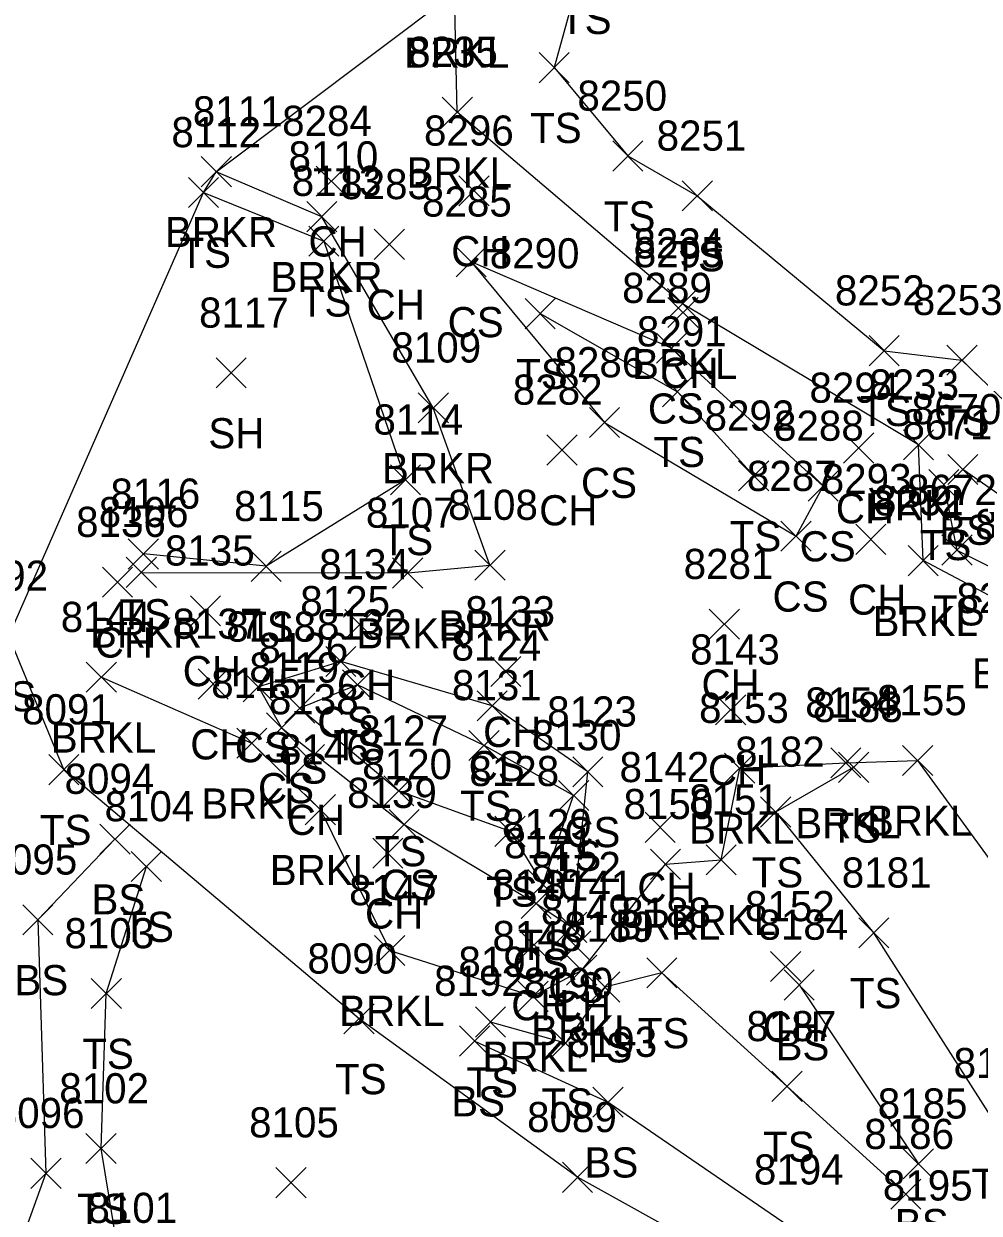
# Model space of a CAD drawing. Extents: x 1482574 to 1485769, y 580696 to 595649.
# Drawn here: x 1484969 to 1485032.3, y 581565.4 to 581644.3 of the extents above; entities that cross this region are included whole.
import ezdxf

# ---------------------------------------------------------------- set-up
doc = ezdxf.new("R2010")
doc.units = 0
for name, color, linetype in [('L_A', 7, 'Continuous'), ('L_I', 7, 'Continuous'), ('L_TIC', 7, 'Continuous'), ('LAWE', 7, 'Continuous'), ('LELB', 7, 'Continuous'), ('LSOGP', 7, 'Continuous')]:
    doc.layers.add(name, color=color, linetype=linetype)

msp = doc.modelspace()

# ---------------------------------------------------------------- linework, layer by layer
at = {"layer": 'L_TIC'}
for points in [[(1485003.126, 581640.419), (1485005.126, 581642.419)], [(1485005.126, 581640.419), (1485003.126, 581642.419)], [(1484996.706, 581637.469), (1484998.706, 581639.469)], [(1484998.706, 581637.469), (1484996.706, 581639.469)], [(1485008.012, 581634.559), (1485010.012, 581636.559)], [(1485010.012, 581634.559), (1485008.012, 581636.559)], [(1484980.735, 581633.519), (1484982.735, 581635.519)], [(1484982.735, 581633.519), (1484980.735, 581635.519)], [(1484988.356, 581632.893), (1484990.356, 581634.893)], [(1484990.356, 581632.893), (1484988.356, 581634.893)], [(1484997.815, 581632.246), (1484999.815, 581634.246)], [(1484999.815, 581632.246), (1484997.815, 581634.246)], [(1484979.882, 581632.141), (1484981.882, 581634.141)], [(1484981.882, 581632.141), (1484979.882, 581634.141)], [(1485012.611, 581631.912), (1485014.611, 581633.912)], [(1485014.611, 581631.912), (1485012.611, 581633.912)], [(1484987.733, 581630.534), (1484989.733, 581632.534)], [(1484989.733, 581630.534), (1484987.733, 581632.534)], [(1484987.857, 581628.91), (1484989.857, 581630.91)], [(1484989.857, 581628.91), (1484987.857, 581630.91)], [(1484992.205, 581628.696), (1484994.205, 581630.696)], [(1484994.205, 581628.696), (1484992.205, 581630.696)], [(1484997.628, 581627.541), (1484999.628, 581629.541)], [(1484999.628, 581627.541), (1484997.628, 581629.541)], [(1485011.643, 581624.763), (1485013.643, 581626.763)], [(1485013.643, 581624.763), (1485011.643, 581626.763)], [(1485002.201, 581624.103), (1485004.201, 581626.103)], [(1485004.201, 581624.103), (1485002.201, 581626.103)], [(1485011.666, 581624.179), (1485013.666, 581626.179)], [(1485013.666, 581624.179), (1485011.666, 581626.179)], [(1485010.899, 581621.813), (1485012.899, 581623.813)], [(1485012.899, 581621.813), (1485010.899, 581623.813)], [(1485024.996, 581621.646), (1485026.996, 581623.646)], [(1485026.996, 581621.646), (1485024.996, 581623.646)], [(1485030.157, 581621.013), (1485032.157, 581623.013)], [(1485032.157, 581621.013), (1485030.157, 581623.013)], [(1484981.716, 581620.173), (1484983.716, 581622.173)], [(1484983.716, 581620.173), (1484981.716, 581622.173)], [(1485011.302, 581618.929), (1485013.302, 581620.929)], [(1485013.302, 581618.929), (1485011.302, 581620.929)], [(1484995.118, 581617.86), (1484997.118, 581619.86)], [(1484997.118, 581617.86), (1484995.118, 581619.86)], [(1485006.463, 581616.882), (1485008.463, 581618.882)], [(1485008.463, 581616.882), (1485006.463, 581618.882)], [(1485003.645, 581615.064), (1485005.645, 581617.064)], [(1485005.645, 581615.064), (1485003.645, 581617.064)], [(1485023.307, 581615.196), (1485025.307, 581617.196)], [(1485025.307, 581615.196), (1485023.307, 581617.196)], [(1485027.273, 581615.406), (1485029.273, 581617.406)], [(1485029.273, 581615.406), (1485027.273, 581617.406)], [(1485016.355, 581613.345), (1485018.355, 581615.345)], [(1485018.355, 581613.345), (1485016.355, 581615.345)], [(1485030.213, 581613.772), (1485032.213, 581615.772)], [(1485032.213, 581613.772), (1485030.213, 581615.772)], [(1484993.277, 581613.086), (1484995.277, 581615.086)], [(1484995.277, 581613.086), (1484993.277, 581615.086)], [(1485020.958, 581612.673), (1485022.958, 581614.673)], [(1485022.958, 581612.673), (1485020.958, 581614.673)], [(1485028.953, 581612.758), (1485030.953, 581614.758)], [(1485030.953, 581612.758), (1485028.953, 581614.758)], [(1485019.16, 581609.343), (1485021.16, 581611.343)], [(1485021.16, 581609.343), (1485019.16, 581611.343)], [(1485024.12, 581609.139), (1485026.12, 581611.139)], [(1485026.12, 581609.139), (1485024.12, 581611.139)], [(1484975.899, 581608.168), (1484977.899, 581610.168)], [(1484977.899, 581608.168), (1484975.899, 581610.168)], [(1485029.823, 581608.424), (1485031.823, 581610.424)], [(1485031.823, 581608.424), (1485029.823, 581610.424)], [(1484984.039, 581607.348), (1484986.039, 581609.348)], [(1484986.039, 581607.348), (1484984.039, 581609.348)], [(1484998.871, 581607.427), (1485000.871, 581609.427)], [(1485000.871, 581607.427), (1484998.871, 581609.427)], [(1485027.582, 581607.722), (1485029.582, 581609.722)], [(1485029.582, 581607.722), (1485027.582, 581609.722)], [(1484974.189, 581606.295), (1484976.189, 581608.295)], [(1484976.189, 581606.295), (1484974.189, 581608.295)], [(1484975.768, 581606.944), (1484977.768, 581608.944)], [(1484977.768, 581606.944), (1484975.768, 581608.944)], [(1484993.422, 581606.908), (1484995.422, 581608.908)], [(1484995.422, 581606.908), (1484993.422, 581608.908)], [(1484980.02, 581604.398), (1484982.02, 581606.398)], [(1484982.02, 581604.398), (1484980.02, 581606.398)], [(1484990.246, 581603.486), (1484992.246, 581605.486)], [(1484992.246, 581603.486), (1484990.246, 581605.486)], [(1485014.403, 581603.506), (1485016.403, 581605.506)], [(1485016.403, 581603.506), (1485014.403, 581605.506)], [(1484988.989, 581601.039), (1484990.989, 581603.039)], [(1484990.989, 581601.039), (1484988.989, 581603.039)], [(1484973.117, 581599.992), (1484975.117, 581601.992)], [(1484975.117, 581599.992), (1484973.117, 581601.992)], [(1484999.928, 581600.366), (1485001.928, 581602.366)], [(1485001.928, 581600.366), (1484999.928, 581602.366)], [(1484980.522, 581599.54), (1484982.522, 581601.54)], [(1484982.522, 581599.54), (1484980.522, 581601.54)], [(1484983.52, 581599.353), (1484985.52, 581601.353)], [(1484985.52, 581599.353), (1484983.52, 581601.353)], [(1484990.095, 581599.487), (1484992.095, 581601.487)], [(1484992.095, 581599.487), (1484990.095, 581601.487)], [(1484986.27, 581597.935), (1484988.27, 581599.935)], [(1484988.27, 581597.935), (1484986.27, 581599.935)], [(1484999.019, 581598.096), (1485001.019, 581600.096)], [(1485001.019, 581598.096), (1484999.019, 581600.096)], [(1485014.829, 581597.834), (1485016.829, 581599.834)], [(1485016.829, 581597.834), (1485014.829, 581599.834)], [(1484985.056, 581596.636), (1484987.056, 581598.636)], [(1484987.056, 581596.636), (1484985.056, 581598.636)], [(1484983.09, 581595.616), (1484985.09, 581597.616)], [(1484985.09, 581595.616), (1484983.09, 581597.616)], [(1484998.481, 581595.468), (1485000.481, 581597.468)], [(1485000.481, 581595.468), (1484998.481, 581597.468)], [(1484986.913, 581594.533), (1484988.913, 581596.533)], [(1484988.913, 581594.533), (1484986.913, 581596.533)], [(1485027.214, 581594.474), (1485029.214, 581596.474)], [(1485029.214, 581594.474), (1485027.214, 581596.474)], [(1484970.633, 581593.864), (1484972.633, 581595.864)], [(1484972.633, 581593.864), (1484970.633, 581595.864)], [(1485005.357, 581593.719), (1485007.357, 581595.719)], [(1485007.357, 581593.719), (1485005.357, 581595.719)], [(1485015.423, 581593.962), (1485017.423, 581595.962)], [(1485017.423, 581593.962), (1485015.423, 581595.962)], [(1485022.46, 581594.316), (1485024.46, 581596.316)], [(1485024.46, 581594.316), (1485022.46, 581596.316)], [(1485022.972, 581594.018), (1485024.972, 581596.018)], [(1485024.972, 581594.018), (1485022.972, 581596.018)], [(1484992.831, 581592.456), (1484994.831, 581594.456)], [(1484994.831, 581592.456), (1484992.831, 581594.456)], [(1485004.419, 581592.148), (1485006.419, 581594.148)], [(1485006.419, 581592.148), (1485004.419, 581594.148)], [(1484987.631, 581591.206), (1484989.631, 581593.206)], [(1484989.631, 581591.206), (1484987.631, 581593.206)], [(1485017.808, 581591.055), (1485019.808, 581593.055)], [(1485019.808, 581591.055), (1485017.808, 581593.055)], [(1484993.186, 581590.229), (1484995.186, 581592.229)], [(1484995.186, 581590.229), (1484993.186, 581592.229)], [(1485000.2, 581589.773), (1485002.2, 581591.773)], [(1485002.2, 581589.773), (1485000.2, 581591.773)], [(1485010.151, 581590.035), (1485012.151, 581592.035)], [(1485012.151, 581590.035), (1485010.151, 581592.035)], [(1484974.016, 581589.257), (1484976.016, 581591.257)], [(1484976.016, 581589.257), (1484974.016, 581591.257)], [(1484992.103, 581588.322), (1484994.103, 581590.322)], [(1484994.103, 581588.322), (1484992.103, 581590.322)], [(1484976.099, 581587.437), (1484978.099, 581589.437)], [(1484978.099, 581587.437), (1484976.099, 581589.437)], [(1485010.505, 581587.584), (1485012.505, 581589.584)], [(1485012.505, 581587.584), (1485010.505, 581589.584)], [(1485014.199, 581587.886), (1485016.199, 581589.886)], [(1485016.199, 581587.886), (1485014.199, 581589.886)], [(1485002.372, 581586.246), (1485004.372, 581588.246)], [(1485004.372, 581586.246), (1485002.372, 581588.246)], [(1485001.936, 581584.986), (1485003.936, 581586.986)], [(1485003.936, 581584.986), (1485001.936, 581586.986)], [(1484968.907, 581583.903), (1484970.907, 581585.903)], [(1484970.907, 581583.903), (1484968.907, 581585.903)], [(1485004.291, 581583.408), (1485006.291, 581585.408)], [(1485006.291, 581583.408), (1485004.291, 581585.408)], [(1485024.314, 581583.04), (1485026.314, 581585.04)], [(1485026.314, 581583.04), (1485024.314, 581585.04)], [(1484992.228, 581581.872), (1484994.228, 581583.872)], [(1484994.228, 581581.872), (1484992.228, 581583.872)], [(1485001.794, 581582.24), (1485003.794, 581584.24)], [(1485003.794, 581582.24), (1485001.794, 581584.24)], [(1485004.55, 581582.171), (1485006.55, 581584.171)], [(1485006.55, 581582.171), (1485004.55, 581584.171)], [(1485004.954, 581580.57), (1485006.954, 581582.57)], [(1485006.954, 581580.57), (1485004.954, 581582.57)], [(1485010.262, 581580.383), (1485012.262, 581582.383)], [(1485012.262, 581580.383), (1485010.262, 581582.383)], [(1485018.468, 581580.813), (1485020.468, 581582.813)], [(1485020.468, 581580.813), (1485018.468, 581582.813)], [(1485006.486, 581579.444), (1485008.486, 581581.444)], [(1485008.486, 581579.444), (1485006.486, 581581.444)], [(1485019.36, 581579.582), (1485021.36, 581581.582)], [(1485021.36, 581579.582), (1485019.36, 581581.582)], [(1484973.441, 581579.018), (1484975.441, 581581.018)], [(1484975.441, 581579.018), (1484973.441, 581581.018)], [(1485001.732, 581578.831), (1485003.732, 581580.831)], [(1485003.732, 581578.831), (1485001.732, 581580.831)], [(1484990.197, 581577.338), (1484992.197, 581579.338)], [(1484992.197, 581577.338), (1484990.197, 581579.338)], [(1484998.907, 581577.125), (1485000.907, 581579.125)], [(1485000.907, 581577.125), (1484998.907, 581579.125)], [(1484997.861, 581575.862), (1484999.861, 581577.862)], [(1484999.861, 581575.862), (1484997.861, 581577.862)], [(1485003.874, 581575.721), (1485005.874, 581577.721)], [(1485005.874, 581575.721), (1485003.874, 581577.721)], [(1485018.563, 581572.857), (1485020.563, 581574.857)], [(1485020.563, 581572.857), (1485018.563, 581574.857)], [(1485006.696, 581571.813), (1485008.696, 581573.813)], [(1485008.696, 581571.813), (1485006.696, 581573.813)], [(1484973.097, 581568.733), (1484975.097, 581570.733)], [(1484975.097, 581568.733), (1484973.097, 581570.733)], [(1485027.264, 581567.725), (1485029.264, 581569.725)], [(1485029.264, 581567.725), (1485027.264, 581569.725)], [(1484969.442, 581567.095), (1484971.442, 581569.095)], [(1484971.442, 581567.095), (1484969.442, 581569.095)], [(1485004.678, 581566.826), (1485006.678, 581568.826)], [(1485006.678, 581566.826), (1485004.678, 581568.826)], [(1484985.679, 581566.472), (1484987.679, 581568.472)], [(1484987.679, 581566.472), (1484985.679, 581568.472)], [(1485026.43, 581565.704), (1485028.43, 581567.704)], [(1485028.43, 581565.704), (1485026.43, 581567.704)]]:
    msp.add_lwpolyline(points, dxfattribs=at)
at = {"layer": 'LAWE'}
for points in [[(1485099.1, 581556.13), (1485088.398, 581562), (1485080.442, 581567.692), (1485075.58, 581577.374), (1485071.961, 581583.594), (1485063.273, 581587.249), (1485048.48, 581598.528), (1485035.166, 581605.248), (1485028.582, 581608.722), (1485028.273, 581616.406), (1485012.643, 581625.763), (1484997.706, 581638.469), (1484997.519, 581646.409), (1484999.248, 581659.608), (1485005.947, 581671.579), (1485014.32, 581682.767), (1485017.407, 581703.738), (1485017.263, 581721.947)], [(1484976.768, 581607.944), (1484994.422, 581607.908), (1484999.871, 581608.427), (1484996.118, 581618.86), (1484988.733, 581631.534), (1484981.735, 581634.519)], [(1484974.117, 581600.992), (1484984.09, 581596.616), (1484988.631, 581592.206), (1484993.228, 581582.872), (1485002.732, 581579.831), (1485005.954, 581581.57), (1485011.505, 581588.584), (1485015.199, 581588.886), (1485016.423, 581594.962), (1485023.46, 581595.316), (1485028.214, 581595.474), (1485036.863, 581583.581), (1485036.065, 581574.657), (1485046.886, 581565.989), (1485054.684, 581560.34), (1485062.22, 581551.186)]]:
    msp.add_lwpolyline(points, dxfattribs=at)
at = {"layer": 'LELB'}
for points in [[(1485021.203, 581722.829), (1485019.576, 581708.682), (1485018.923, 581696.31), (1485015.291, 581681.681), (1485009.596, 581676.337), (1485004.149, 581657.718), (1485006.105, 581648.646), (1485004.126, 581641.419), (1485009.012, 581635.559), (1485013.611, 581632.912), (1485025.996, 581622.646), (1485031.157, 581622.013), (1485040.905, 581612.626), (1485044.792, 581604.06), (1485054.025, 581597.429), (1485058.231, 581593.289), (1485067.079, 581592.183), (1485075.865, 581590.559), (1485078.352, 581585.917), (1485082.988, 581583.45), (1485084.989, 581579.68), (1485093.818, 581577.557), (1485099.497, 581571.757), (1485106.862, 581568.984)], [(1484980.882, 581633.141), (1484988.857, 581629.91), (1484994.277, 581614.086), (1484985.039, 581608.348), (1484976.899, 581609.168)], [(1484998.628, 581628.541), (1485007.463, 581617.882), (1485020.16, 581610.343), (1485021.958, 581613.673), (1485011.899, 581622.813)], [(1485011.899, 581622.813), (1484998.628, 581628.541)], [(1485003.201, 581625.103), (1485012.302, 581619.929), (1485017.355, 581614.345)], [(1485037.519, 581606.543), (1485037.45, 581610.435), (1485031.213, 581614.772)], [(1485029.953, 581613.758), (1485030.823, 581609.424), (1485035.337, 581607.137)], [(1485097.076, 581506.941), (1485080.77, 581517.807), (1485078.027, 581523.771), (1485062.01, 581528.804), (1485049.09, 581536.209), (1485040.813, 581538.65), (1485032.027, 581549.267), (1485022.483, 581558.483), (1485005.678, 581567.826), (1484991.197, 581578.338), (1484971.633, 581594.864), (1484967.972, 581603.725)], [(1484984.52, 581600.353), (1484986.056, 581597.636), (1484994.186, 581591.229), (1485002.936, 581585.986), (1485005.291, 581584.408), (1485006.357, 581594.719), (1485000.019, 581599.096), (1484989.989, 581602.039)], [(1484989.989, 581602.039), (1484984.52, 581600.353)], [(1484987.27, 581598.935), (1484993.831, 581593.456), (1485001.2, 581590.773), (1485003.372, 581587.246), (1485005.419, 581593.148), (1484999.481, 581596.468), (1484991.095, 581600.487)], [(1484991.095, 581600.487), (1484987.27, 581598.935)], [(1485044.901, 581562.551), (1485033.382, 581571.406), (1485025.314, 581584.04), (1485018.808, 581592.055), (1485023.972, 581595.018)], [(1484975.016, 581590.257), (1484969.907, 581584.903), (1484970.442, 581568.095), (1484966.049, 581555.943), (1484956.4, 581551.842)], [(1484955.856, 581543.834), (1484964.14, 581549.172), (1484975.396, 581561.803), (1484974.097, 581569.733), (1484974.441, 581580.018), (1484977.099, 581588.437)], [(1485027.43, 581566.704), (1485019.563, 581573.857), (1485011.262, 581581.383), (1485007.486, 581580.444), (1485004.874, 581576.721), (1484999.907, 581578.125)], [(1485020.36, 581580.582), (1485028.264, 581568.725)], [(1484998.861, 581576.862), (1485007.696, 581572.813), (1485020.058, 581564.349), (1485028.605, 581563.289), (1485031.813, 581560.09)]]:
    msp.add_lwpolyline(points, dxfattribs=at)
at = {"layer": 'LSOGP'}
msp.add_lwpolyline([(1484923.771, 581416.282), (1484922.142, 581457.704), (1484921.818, 581525.617), (1484923.517, 581536.406), (1484956.4, 581551.842), (1484958.467, 581576.934), (1484967.972, 581603.725), (1484980.882, 581633.141), (1484981.735, 581634.519), (1484997.519, 581646.409), (1484999.248, 581659.608), (1485005.947, 581671.579), (1485014.32, 581682.767), (1485017.407, 581703.738), (1485017.263, 581721.947), (1485021.203, 581722.829), (1485060.77, 581735.5), (1485092.404, 581773.469)], dxfattribs=at)

# ---------------------------------------------------------------- texts
at = {"layer": 'L_A'}
for s, p in [('TS', (1485004.514, 581643.646)), ('BRKL', (1484994.165, 581641.409)), ('TS', (1485002.535, 581636.419)), ('BRKL', (1484994.352, 581633.469)), ('TS', (1485007.421, 581630.559)), ('BRKR', (1484978.326, 581629.519)), ('CH', (1484987.844, 581628.893)), ('CH', (1484997.303, 581628.246)), ('TS', (1484979.291, 581628.141)), ('TS', (1485012.02, 581627.912)), ('BRKR', (1484985.324, 581626.534)), ('TS', (1484987.266, 581624.91)), ('CH', (1484991.693, 581624.696)), ('CS', (1484997.069, 581623.541)), ('BRKL', (1485009.289, 581620.763)), ('TS', (1485001.61, 581620.103)), ('CH', (1485011.154, 581620.179)), ('CS', (1485010.34, 581617.813)), ('TS', (1485024.405, 581617.646)), ('TS', (1485029.566, 581617.013)), ('SH', (1484981.204, 581616.173)), ('TS', (1485010.711, 581614.929)), ('BRKR', (1484992.709, 581613.86)), ('CS', (1485005.904, 581612.882)), ('CH', (1485003.133, 581611.064)), ('CH', (1485022.795, 581611.196)), ('BRKL', (1485024.919, 581611.406)), ('TS', (1485015.764, 581609.345)), ('BS', (1485029.654, 581609.772)), ('TS', (1484992.686, 581609.086)), ('CS', (1485020.399, 581608.673)), ('TS', (1485028.362, 581608.758)), ('CS', (1485018.601, 581605.343)), ('CH', (1485023.608, 581605.139)), ('TS', (1484975.308, 581604.168)), ('TS', (1485029.232, 581604.424)), ('TS', (1484983.448, 581603.348)), ('BRKR', (1484996.462, 581603.427)), ('BRKL', (1485025.228, 581603.722)), ('BRKR', (1484973.359, 581602.944)), ('CH', (1484973.677, 581602.295)), ('BRKR', (1484991.013, 581602.908)), ('CH', (1484979.508, 581600.398)), ('BRKL', (1485031.812, 581600.248)), ('CH', (1484989.734, 581599.486)), ('CH', (1485013.891, 581599.506)), ('TS', (1484966.381, 581598.725)), ('CS', (1484988.43, 581597.039)), ('BRKL', (1484970.763, 581595.992)), ('CH', (1484999.416, 581596.366)), ('CH', (1484980.01, 581595.54)), ('CS', (1484982.961, 581595.353)), ('TS', (1484989.504, 581595.487)), ('TS', (1484985.679, 581593.935)), ('CS', (1484998.46, 581594.096)), ('CH', (1485014.317, 581593.834)), ('CS', (1484984.497, 581592.636)), ('BRKL', (1484980.736, 581591.616)), ('TS', (1484997.89, 581591.468)), ('CH', (1484986.401, 581590.533)), ('BRKL', (1485024.86, 581590.474)), ('TS', (1484970.042, 581589.864)), ('CS', (1485004.798, 581589.719)), ('BRKL', (1485013.069, 581589.962)), ('BRKL', (1485020.106, 581590.316)), ('TS', (1485022.381, 581590.018)), ('TS', (1484992.24, 581588.456)), ('TS', (1485003.828, 581588.148)), ('BRKL', (1484985.277, 581587.206)), ('TS', (1485017.217, 581587.055)), ('CS', (1484992.627, 581586.229)), ('TS', (1484999.609, 581585.773)), ('CH', (1485009.639, 581586.035)), ('BS', (1484973.457, 581585.257)), ('CH', (1484991.591, 581584.322)), ('TS', (1484975.508, 581583.437)), ('BRKL', (1485008.151, 581583.584)), ('BRKL', (1485011.845, 581583.886)), ('TS', (1485001.781, 581582.246)), ('CS', (1485001.377, 581580.986)), ('BS', (1484968.348, 581579.903)), ('CS', (1485003.732, 581579.408)), ('TS', (1485023.723, 581579.04)), ('BRKL', (1484989.874, 581577.872)), ('CH', (1485001.282, 581578.24)), ('CH', (1485004.038, 581578.171)), ('BRKL', (1485002.6, 581576.57)), ('TS', (1485009.671, 581576.383)), ('CH', (1485017.956, 581576.813)), ('TS', (1485005.895, 581575.444)), ('BS', (1485018.801, 581575.582)), ('TS', (1484972.85, 581575.018)), ('BRKL', (1484999.378, 581574.831)), ('TS', (1484989.606, 581573.338)), ('TS', (1484998.316, 581573.125)), ('BS', (1484997.302, 581571.862)), ('TS', (1485003.283, 581571.721)), ('TS', (1485017.972, 581568.857)), ('BS', (1485006.137, 581567.813)), ('TS', (1485031.791, 581566.406)), ('TS', (1484972.506, 581564.733)), ('BS', (1485026.705, 581563.725))]:
    msp.add_text(s, height=2, dxfattribs=at).set_placement(p)
at = {"layer": 'L_I'}
for s, p in [('8235', (1484994.446, 581641.469)), ('8250', (1485005.666, 581638.559)), ('8111', (1484980.176, 581637.519)), ('8112', (1484978.756, 581636.141)), ('8284', (1484986.096, 581636.893)), ('8296', (1484995.5, 581636.246)), ('8251', (1485010.918, 581635.912)), ('8110', (1484986.52, 581634.534)), ('8113', (1484986.731, 581632.91)), ('8283', (1484989.945, 581632.696)), ('8285', (1484995.368, 581631.541)), ('8234', (1485009.383, 581628.763)), ('8290', (1484999.855, 581628.103)), ('8295', (1485009.406, 581628.179)), ('8289', (1485008.631, 581625.813)), ('8252', (1485022.736, 581625.646)), ('8253', (1485027.897, 581625.013)), ('8117', (1484980.59, 581624.173)), ('8291', (1485009.609, 581622.929)), ('8109', (1484993.338, 581621.86)), ('8286', (1485004.148, 581620.882)), ('8282', (1485001.385, 581619.064)), ('8294', (1485021.047, 581619.196)), ('8233', (1485025.013, 581619.406)), ('8292', (1485014.095, 581617.345)), ('8670', (1485027.819, 581617.772)), ('8114', (1484992.151, 581617.086)), ('8288', (1485018.698, 581616.673)), ('8671', (1485027.213, 581616.758)), ('8287', (1485016.9, 581613.343)), ('8293', (1485021.86, 581613.139)), ('8116', (1484974.718, 581612.168)), ('8232', (1485025.322, 581611.722)), ('8672', (1485027.516, 581612.424)), ('8106', (1484973.941, 581610.944)), ('8115', (1484982.913, 581611.348)), ('8107', (1484991.65, 581610.908)), ('8108', (1484997.099, 581611.427)), ('8136', (1484972.441, 581610.295)), ('8673', (1485032.03, 581610.137)), ('8135', (1484978.327, 581608.398)), ('8134', (1484988.553, 581607.486)), ('8281', (1485012.71, 581607.506)), ('8092', (1484964.633, 581606.725)), ('8125', (1484987.296, 581605.039)), ('8280', (1485030.79, 581605.242)), ('8144', (1484971.424, 581603.992)), ('8133', (1484998.235, 581604.366)), ('8137', (1484978.829, 581603.54)), ('8118', (1484982.394, 581603.353)), ('8132', (1484988.402, 581603.487)), ('8126', (1484984.522, 581601.935)), ('8124', (1484997.326, 581602.096)), ('8143', (1485013.136, 581601.834)), ('8119', (1484983.922, 581600.636)), ('8145', (1484981.397, 581599.616)), ('8131', (1484997.355, 581599.468)), ('8138', (1484985.22, 581598.533)), ('8154', (1485020.767, 581598.316)), ('8155', (1485025.521, 581598.474)), ('8091', (1484968.861, 581597.864)), ('8123', (1485003.664, 581597.719)), ('8153', (1485013.73, 581597.962)), ('8183', (1485021.279, 581598.018)), ('8127', (1484991.138, 581596.456)), ('8130', (1485002.639, 581596.148)), ('8146', (1484985.883, 581595.206)), ('8182', (1485016.115, 581595.055)), ('8120', (1484991.406, 581594.229)), ('8128', (1484998.507, 581593.773)), ('8142', (1485008.458, 581594.035)), ('8094', (1484971.677, 581593.257)), ('8139', (1484990.402, 581592.322)), ('8104', (1484974.327, 581591.437)), ('8150', (1485008.725, 581591.584)), ('8151', (1485013.073, 581591.886)), ('8129', (1485000.671, 581590.246)), ('8121', (1485000.81, 581588.986)), ('8095', (1484966.568, 581587.903)), ('8122', (1485002.598, 581587.408)), ('8181', (1485023.188, 581587.04)), ('8147', (1484990.535, 581585.872)), ('8140', (1485000.014, 581586.24)), ('8141', (1485003.424, 581586.171)), ('8149', (1485003.253, 581584.57)), ('8188', (1485008.569, 581584.383)), ('8152', (1485016.775, 581584.813)), ('8189', (1485004.785, 581583.444)), ('8184', (1485017.667, 581583.582)), ('8103', (1484971.669, 581583.018)), ('8148', (1485000.039, 581582.831)), ('8090', (1484987.772, 581581.338)), ('8191', (1484997.781, 581581.125)), ('8192', (1484996.168, 581579.862)), ('8190', (1485002.094, 581579.721)), ('8187', (1485016.87, 581576.857)), ('8193', (1485005.003, 581575.813)), ('8180', (1485030.602, 581574.406)), ('8102', (1484971.325, 581572.733)), ('8185', (1485025.571, 581571.725)), ('8096', (1484967.048, 581571.095)), ('8089', (1485002.332, 581570.826)), ('8105', (1484983.907, 581570.472)), ('8186', (1485024.682, 581569.704)), ('8194', (1485017.365, 581567.349)), ('8195', (1485025.912, 581566.289)), ('8101', (1484973.191, 581564.803))]:
    msp.add_text(s, height=2, dxfattribs=at).set_placement(p)

doc.saveas('drawing.dxf')
